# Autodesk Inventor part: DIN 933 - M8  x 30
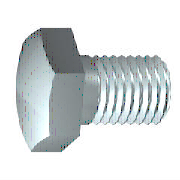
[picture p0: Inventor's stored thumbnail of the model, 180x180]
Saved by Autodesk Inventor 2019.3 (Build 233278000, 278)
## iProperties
Created: 2018-01
Part Number: DIN 933 - M8  x 30
Material: Ocel, měkká
Description: Šestihranný šroub
Document SubType Name: Modeling
Standard: DIN 933
Designer: B-hon
Standards Organization: DIN
Language: cs-CZ
Size Designation: M8  x 30
Categories: <MemberInstance><Categories><Category DisplayName="Spojovací materiál" InternalName="e4da775c-781d-43d5-af7c-5136215cf5a6" Mnemonic="FSTN"><Category DisplayName
Density: 7.85 g/cm^3
Appearance: Pololeštěná
IsCustomPart: 0
Author: B-hon
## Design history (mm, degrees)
sketch "Náčrt1"
  geometry: L1 (0, 5.7)-(0, 3.662); L2 (3.75, 4)-(30, 4); L3 (30, 4)-(30, 0); L4 (30, 0)-(-0.6, 0); L5 (-6.72, 0)-(36.12, 0) reference; L6 (-0.6, 0)-(-0.6, 5.7); L7 (-0.6, 5.7)-(0, 5.7); L8 (3.75, 4)-(2.983, 3.662); L9 (2.983, 3.662)-(0, 3.662); L10 (0, -1.14)-(0, 6.84) reference
  constraints: 16 end point, 2 collinear, 2 perpendicular, 1 parallel
  dimensions: "d0" = 30 distance between parallel lines of L3 L1 (= NLG); "d1" = 26.25 distance from line of L2.start L3 (= GEL); "d2" = 8 diameter of L2 L4 (= GD); "d9" = 0.6001 distance between parallel lines of L6 L1 (computed from SD); "d10" = 11.4 diameter of L7 L4 (= SD2); "d13" = 0.76691 horizontal distance of L2.start L8.end (computed from GAL); "d14" = 7.32342 diameter of L9 L4 (= BDM)
revolve "Těleso" sketch "Náčrt1" stored, may be unused: angle "d12" = 90 deg
sketch "Náčrt2"
  geometry: L1 (0, 7.506)-(6.5, 3.753); L2 (6.5, 3.753)-(6.5, -3.753); L3 (6.5, -3.753)-(0, -7.506); L4 (0, -7.506)-(-6.5, -3.753); L5 (-6.5, -3.753)-(-6.5, 3.753); L6 (-6.5, 3.753)-(0, 7.506); 2 further points
  constraints: 12 end point, 1 coincident, 1 vertical, 11 other
  dimensions: "d11" = 13 distance between parallel lines of L5 L2 (= SW)
extrude "Hlava" join sketch "Náčrt2" distance "d3" = 4.7 (= KOH - SD); taper "d4" = 0 deg
sketch "Náčrt4"
  geometry: L1 (-5.3, 6.5)-(-5.3, 7.506); L2 (-5.3, 7.506)-(-4.72, 7.506); L3 (-4.72, 7.506)-(-5.3, 6.5); L4 (-6.24, 0)-(0.34, 0) reference; L5 (-0.6, 7.506)-(-5.3, 7.506) reference; L6 (-5.3, 3.753)-(-5.3, 7.506) reference
  constraints: 6 end point, 2 collinear, 1 perpendicular, 1 vertical
  dimensions: "d5" = 30 deg angle of L3 L1 (= ANG1); "d19" = 13 diameter of L1.start L4 (= SW0)
revolve "Zkosení1" sketch "Náčrt4" stored, may be unused: angle "d21" = 90 deg
workplane "Work Plane1"
body "Solid1"
feature "Závit" dims "d15" = 26.25 (= GEL), "d16" = 0
chamfer "Zkosení2" distance "d6" = 0.76681 (= -0.5 x SPD + 0.5 x GD); stored, may be unused: second distance "d7" = 0.76691 (computed from GUL), angle "d55" = 45 deg
other parameters: "NLG" = 30 [user parameter; used in 1 equation term], "GD" = 8 (= NND) [user parameter; used in 2 equation terms], "BDM" = 7.32342 [user parameter; used in 1 equation term], "KOH" = 5.3 [user parameter; used in 1 equation term], "GEL" = 26.25 [user parameter; used in 2 equation terms], "SW" = 13 [user parameter; used in 2 equation terms], "SW0" = 13 [user parameter; used in 1 equation term], "SPD" = 6.46637 (= NND - 1.2269 x PTC) [user parameter; used in 1 equation term], "SD2" = 11.4 [user parameter; used in 1 equation term], "SD" = 0.6 [user parameter; used in 2 equation terms], "ANG1" = 30 deg [user parameter; used in 1 equation term], "GAL" = 0.76681 (= 0.61345 x PTC) [user parameter; used in 1 equation term], "GUL" = 0.76681 (= 0.61345 x PTC) [user parameter; used in 1 equation term], "d8" = 0, "RR" = 0.4 [user parameter], "d57" = 0, "d58" = 0, "TPU" = 8 (computed from PTC) [user parameter], "GD1" = 6.46637 (= THREADDIA - 1.2269 x PTC) [user parameter], "THREADDIA" = 8 [user parameter; used in 1 equation term], "TOA" = 30 deg [user parameter], "PTC" = 1.25 [user parameter; used in 5 equation terms], "NND" = 8 [user parameter; used in 2 equation terms], "E0" = 15.015 (= 1.155 x SW) [user parameter]
